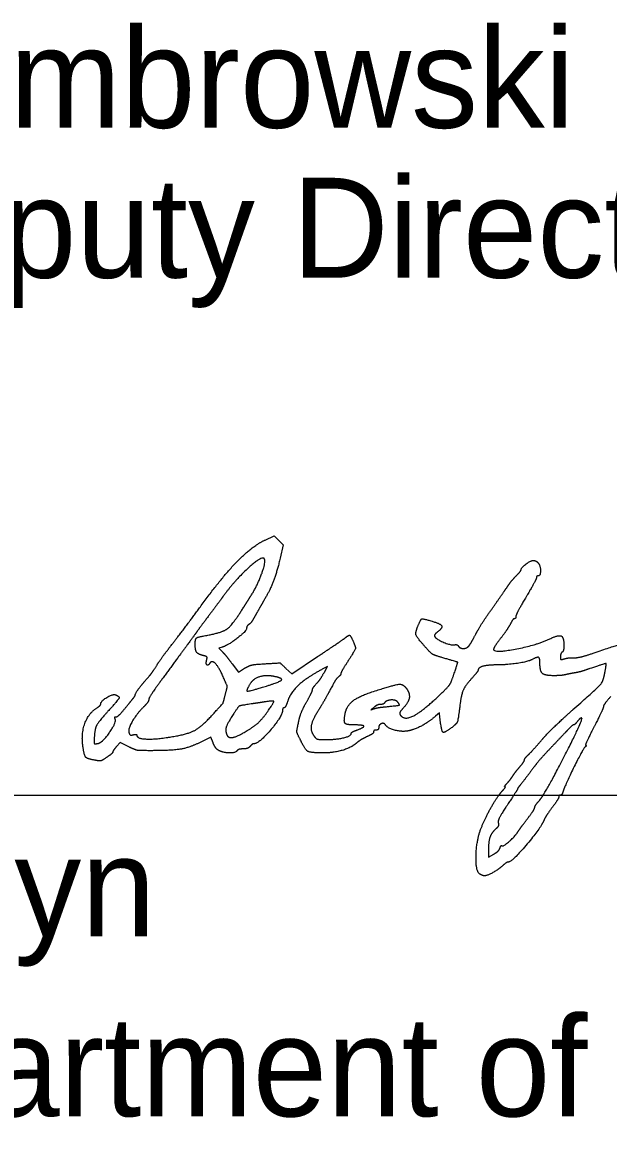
# Model space of a CAD drawing. Extents: x 0 to 34, y 0 to 22.
# Drawn here: x 25.732 to 26.552, y 7.26 to 8.834 of the extents above; entities that cross this region are included whole.
import ezdxf

# ---------------------------------------------------------------- set-up
doc = ezdxf.new("R2010")
doc.units = 0
for name, color, linetype in [('Default', 7, 'Continuous'), ('SH_Data', 7, 'Continuous'), ('SH_Text', 7, 'Continuous')]:
    doc.layers.add(name, color=color, linetype=linetype)

msp = doc.modelspace()

# ---------------------------------------------------------------- linework, layer by layer
at = {"layer": 'Default'}
for points in [[(26.0715, 8.1089), (26.0842, 8.1148), (26.0905, 8.1084), (26.0969, 8.102), (26.0925, 8.0833)], [(26.0116, 7.9589), (26.0066, 7.9574), (26.0118, 7.9522)], [(26.0254, 7.9355), (26.034, 7.924), (26.0428, 7.9293)], [(26.1006, 7.9292), (26.1087, 7.9216), (26.145, 7.9457)], [(26.1544, 7.924), (26.1589, 7.9319), (26.1534, 7.929)], [(26.3162, 7.8603), (26.3156, 7.8671), (26.3097, 7.862)], [(25.88, 7.8196), (25.8685, 7.8254), (25.8634, 7.8196)], [(25.9986, 7.8247), (25.9953, 7.8327), (25.9814, 7.8259)], [(26.384, 7.6742), (26.384, 7.6648), (26.3915, 7.6691)]]:
    msp.add_lwpolyline(points, dxfattribs=at)
for points in [[(25.982, 8.017), (26.0116, 8.0576), (26.0535, 8.1005), (26.0715, 8.1089)], [(26.0701, 8.0831), (26.0664, 8.0868), (26.0279, 8.051), (26.0125, 8.0297)], [(26.0518, 8.0311), (26.0612, 8.0459), (26.0732, 8.08), (26.0701, 8.0831)], [(26.0925, 8.0833), (26.0875, 8.0622), (26.0783, 8.0386), (26.0689, 8.0227)], [(26.4296, 8.067), (26.4296, 8.0698), (26.4428, 8.0801), (26.4465, 8.0802)], [(26.4465, 8.0802), (26.4485, 8.0802), (26.4515, 8.079), (26.4531, 8.0774)], [(26.4531, 8.0774), (26.4566, 8.0739), (26.457, 8.0587), (26.4536, 8.0587)], [(26.423, 8.0589), (26.4266, 8.0625), (26.4296, 8.0662), (26.4296, 8.067)], [(26.4092, 8.0417), (26.4131, 8.0475), (26.4193, 8.0553), (26.423, 8.0589)], [(26.4512, 8.0561), (26.4512, 8.0548), (26.4447, 8.0427), (26.4368, 8.0293)], [(26.4536, 8.0587), (26.4523, 8.0587), (26.4512, 8.0575), (26.4512, 8.0561)], [(26.0125, 8.0297), (26.0089, 8.0248), (25.9995, 8.0121), (25.9916, 8.0016)], [(26.0413, 8.0144), (26.0445, 8.0196), (26.0493, 8.0271), (26.0518, 8.0311)], [(26.3876, 8.0107), (26.3955, 8.0219), (26.4052, 8.0358), (26.4092, 8.0417)], [(26.4368, 8.0293), (26.4289, 8.0159), (26.4224, 8.0035), (26.4224, 8.0018)], [(25.9418, 7.9636), (25.9507, 7.9749), (25.9688, 7.999), (25.982, 8.017)], [(25.9915, 7.9757), (26.0121, 7.9795), (26.0261, 7.9904), (26.0413, 8.0144)], [(26.0689, 8.0227), (26.0654, 8.0167), (26.0602, 8.0075), (26.0573, 8.0023)], [(25.9916, 8.0016), (25.9837, 7.9912), (25.9756, 7.9801), (25.9736, 7.9772)], [(26.0573, 8.0023), (26.0545, 7.997), (26.0507, 7.9918), (26.0489, 7.9907)], [(26.2855, 7.9889), (26.2893, 7.998), (26.2924, 7.999), (26.3051, 7.9952)], [(26.3662, 7.9771), (26.37, 7.9843), (26.3796, 7.9994), (26.3876, 8.0107)], [(26.4204, 7.9987), (26.4193, 7.9987), (26.4169, 7.9957), (26.4151, 7.9921)], [(26.4224, 8.0018), (26.4224, 8.0001), (26.4215, 7.9987), (26.4204, 7.9987)], [(26.0456, 7.9853), (26.0456, 7.9816), (26.0198, 7.9615), (26.0116, 7.9589)], [(26.0489, 7.9907), (26.0471, 7.9897), (26.0456, 7.9873), (26.0456, 7.9853)], [(26.2953, 7.9595), (26.2838, 7.9726), (26.2815, 7.9793), (26.2855, 7.9889)], [(26.3051, 7.9952), (26.3171, 7.9917), (26.32, 7.9855), (26.3123, 7.9797)], [(26.4151, 7.9921), (26.4133, 7.9884), (26.4072, 7.9793), (26.4015, 7.9719)], [(25.9736, 7.9772), (25.9716, 7.9742), (25.9562, 7.9533), (25.9394, 7.9306)], [(25.9736, 7.9636), (25.9736, 7.9705), (25.9777, 7.9733), (25.9915, 7.9757)], [(26.145, 7.9457), (26.1649, 7.959), (26.1825, 7.9709), (26.1841, 7.9723)], [(26.1841, 7.9723), (26.1886, 7.976), (26.191, 7.9751), (26.194, 7.9685)], [(26.194, 7.9685), (26.1984, 7.9589), (26.1974, 7.9548), (26.1872, 7.939)], [(26.3123, 7.9797), (26.3095, 7.9776), (26.3081, 7.9748), (26.309, 7.9734)], [(26.309, 7.9734), (26.3117, 7.9696), (26.3316, 7.9614), (26.3362, 7.9622)], [(26.3569, 7.9609), (26.3582, 7.9625), (26.3624, 7.9698), (26.3662, 7.9771)], [(26.4015, 7.9719), (26.3958, 7.9644), (26.3912, 7.9571), (26.3912, 7.9558)], [(26.3912, 7.9558), (26.3912, 7.9505), (26.4508, 7.9615), (26.4688, 7.97)], [(26.4688, 7.97), (26.4817, 7.9762), (26.4896, 7.9731), (26.4896, 7.9617)], [(25.9203, 7.9342), (25.9232, 7.939), (25.9329, 7.9522), (25.9418, 7.9636)], [(25.9846, 7.9472), (25.9774, 7.949), (25.9736, 7.9547), (25.9736, 7.9636)], [(26.0118, 7.9522), (26.0146, 7.9494), (26.0207, 7.9419), (26.0254, 7.9355)], [(26.3188, 7.9444), (26.308, 7.9475), (26.3031, 7.9506), (26.2953, 7.9595)], [(26.3362, 7.9622), (26.3385, 7.9626), (26.341, 7.9618), (26.3419, 7.9604)], [(26.3419, 7.9604), (26.3441, 7.9569), (26.3541, 7.9572), (26.3569, 7.9609)], [(26.4872, 7.9519), (26.4859, 7.951), (26.4848, 7.9482), (26.4848, 7.9456)], [(26.4896, 7.9617), (26.4896, 7.9571), (26.4885, 7.9527), (26.4872, 7.9519)], [(26.5031, 7.9439), (26.5073, 7.9438), (26.5202, 7.9469), (26.5319, 7.9509)], [(26.5319, 7.9509), (26.5723, 7.9648), (26.5782, 7.9632), (26.5741, 7.9393)], [(25.904, 7.9123), (25.9106, 7.9197), (25.9148, 7.9254), (25.9203, 7.9342)], [(25.9897, 7.941), (25.9906, 7.9445), (25.9893, 7.946), (25.9846, 7.9472)], [(25.9939, 7.9362), (25.9915, 7.9323), (25.9883, 7.9359), (25.9897, 7.941)], [(26.0127, 7.9176), (26.0066, 7.9313), (25.9969, 7.9409), (25.9939, 7.9362)], [(26.0428, 7.9293), (26.0493, 7.9331), (26.0569, 7.9348), (26.072, 7.9357)], [(26.072, 7.9357), (26.0923, 7.9369), (26.0925, 7.9368), (26.1006, 7.9292)], [(26.1872, 7.939), (26.1819, 7.9308), (26.1776, 7.9232), (26.1776, 7.9221)], [(26.3356, 7.9206), (26.3412, 7.9374), (26.3409, 7.938), (26.3188, 7.9444)], [(26.3938, 7.9339), (26.3823, 7.9339), (26.3696, 7.9301), (26.3696, 7.9267)], [(26.4445, 7.9412), (26.439, 7.9383), (26.4088, 7.9339), (26.3938, 7.9339)], [(26.456, 7.9365), (26.456, 7.9439), (26.4523, 7.9454), (26.4445, 7.9412)], [(26.4753, 7.9189), (26.4629, 7.9189), (26.456, 7.9252), (26.456, 7.9365)], [(26.4848, 7.9456), (26.4848, 7.9417), (26.4858, 7.9411), (26.4902, 7.9425)], [(26.4902, 7.9425), (26.4931, 7.9434), (26.499, 7.9441), (26.5031, 7.9439)], [(26.5472, 7.9243), (26.5493, 7.9358), (26.5475, 7.9362), (26.5265, 7.929)], [(25.9394, 7.9306), (25.9226, 7.908), (25.9088, 7.8878), (25.9088, 7.8859)], [(26.0838, 7.9179), (26.0729, 7.9201), (26.0555, 7.915), (26.0512, 7.9084)], [(26.1534, 7.929), (26.13, 7.9164), (26.1072, 7.8958), (26.1031, 7.8833)], [(26.1417, 7.9058), (26.1471, 7.9118), (26.1496, 7.9154), (26.1544, 7.924)], [(26.1776, 7.9221), (26.1776, 7.921), (26.176, 7.9187), (26.174, 7.9171)], [(26.3173, 7.8933), (26.3277, 7.9033), (26.3318, 7.9095), (26.3356, 7.9206)], [(26.3696, 7.9267), (26.3696, 7.9258), (26.3654, 7.9204), (26.3602, 7.9146)], [(26.492, 7.9203), (26.4887, 7.9195), (26.4812, 7.9189), (26.4753, 7.9189)], [(26.5052, 7.9229), (26.5012, 7.9223), (26.4953, 7.9211), (26.492, 7.9203)], [(26.5023, 7.8714), (26.5378, 7.9029), (26.5448, 7.9111), (26.5472, 7.9243)], [(26.5265, 7.929), (26.5188, 7.9263), (26.5091, 7.9235), (26.5052, 7.9229)], [(25.8896, 7.8919), (25.8896, 7.8935), (25.8987, 7.9065), (25.904, 7.9123)], [(26.016, 7.8931), (26.0186, 7.9029), (26.0183, 7.9051), (26.0127, 7.9176)], [(26.0512, 7.9084), (26.0442, 7.8977), (26.0487, 7.8969), (26.0732, 7.9044)], [(26.0732, 7.9044), (26.0924, 7.9103), (26.0964, 7.9154), (26.0838, 7.9179)], [(26.1377, 7.8988), (26.1379, 7.9006), (26.1397, 7.9037), (26.1417, 7.9058)], [(26.1671, 7.9078), (26.159, 7.8924), (26.1512, 7.8786), (26.1451, 7.8689)], [(26.174, 7.9171), (26.1721, 7.9155), (26.169, 7.9113), (26.1671, 7.9078)], [(26.221, 7.8961), (26.2528, 7.9067), (26.2662, 7.9071), (26.2713, 7.8977)], [(26.3602, 7.9146), (26.3517, 7.9052), (26.346, 7.8926), (26.3444, 7.8799)], [(25.8416, 7.8798), (25.8417, 7.8836), (25.8584, 7.8936), (25.8622, 7.8921)], [(25.8622, 7.8921), (25.8681, 7.8898), (25.8659, 7.8849), (25.8515, 7.869)], [(25.8751, 7.8727), (25.8804, 7.8793), (25.8859, 7.886), (25.8872, 7.8876)], [(25.8872, 7.8876), (25.8885, 7.8892), (25.8896, 7.8911), (25.8896, 7.8919)], [(25.9964, 7.8626), (26.0125, 7.8801), (26.0128, 7.8807), (26.016, 7.8931)], [(26.1292, 7.8817), (26.1336, 7.8894), (26.1374, 7.8971), (26.1377, 7.8988)], [(26.1833, 7.8651), (26.1855, 7.8763), (26.2016, 7.8897), (26.221, 7.8961)], [(26.2603, 7.8644), (26.2656, 7.8558), (26.2923, 7.8693), (26.3173, 7.8933)], [(26.2713, 7.8977), (26.2745, 7.8916), (26.2711, 7.8802), (26.2637, 7.8723)], [(26.5553, 7.8899), (26.5495, 7.8834), (26.5448, 7.8769), (26.5448, 7.8753)], [(25.8167, 7.8182), (25.8138, 7.8368), (25.8245, 7.8668), (25.8369, 7.8745)], [(25.8369, 7.8745), (25.8395, 7.8761), (25.8416, 7.8785), (25.8416, 7.8798)], [(25.8628, 7.8614), (25.8642, 7.861), (25.8697, 7.8661), (25.8751, 7.8727)], [(25.9014, 7.8751), (25.8916, 7.8655), (25.8792, 7.8434), (25.881, 7.8387)], [(25.9088, 7.8859), (25.9087, 7.8839), (25.9054, 7.8791), (25.9014, 7.8751)], [(26.054, 7.8796), (26.0362, 7.877), (26.0342, 7.8759), (26.0269, 7.8647)], [(26.0714, 7.8823), (26.0658, 7.8814), (26.0579, 7.8802), (26.054, 7.8796)], [(26.0959, 7.8709), (26.0958, 7.8623), (26.0627, 7.8235), (26.0556, 7.8235)], [(26.0764, 7.8706), (26.0842, 7.882), (26.0833, 7.8841), (26.0714, 7.8823)], [(26.098, 7.8739), (26.0969, 7.8739), (26.096, 7.8725), (26.0959, 7.8709)], [(26.1031, 7.8833), (26.1014, 7.8781), (26.0991, 7.8739), (26.098, 7.8739)], [(26.1183, 7.8539), (26.1199, 7.8616), (26.1248, 7.8741), (26.1292, 7.8817)], [(26.2242, 7.8749), (26.2196, 7.8711), (26.2196, 7.8711), (26.2244, 7.8728)], [(26.2331, 7.8787), (26.2308, 7.8787), (26.2268, 7.877), (26.2242, 7.8749)], [(26.2244, 7.8728), (26.227, 7.8737), (26.2346, 7.8749), (26.2412, 7.8755)], [(26.2386, 7.8808), (26.2379, 7.8796), (26.2354, 7.8787), (26.2331, 7.8787)], [(26.2571, 7.8819), (26.2543, 7.8853), (26.2409, 7.8845), (26.2386, 7.8808)], [(26.2412, 7.8755), (26.2579, 7.8771), (26.2603, 7.878), (26.2571, 7.8819)], [(26.2637, 7.8723), (26.2609, 7.8694), (26.2594, 7.8659), (26.2603, 7.8644)], [(26.3444, 7.8799), (26.3416, 7.8574), (26.3398, 7.8519), (26.3342, 7.8474)], [(26.4583, 7.8286), (26.4655, 7.837), (26.4853, 7.8562), (26.5023, 7.8714)], [(26.5448, 7.8753), (26.5448, 7.8737), (26.5388, 7.8609), (26.5315, 7.8467)], [(25.8515, 7.869), (25.8379, 7.8539), (25.8329, 7.8437), (25.8323, 7.8299)], [(25.8371, 7.8239), (25.8435, 7.8248), (25.8636, 7.8533), (25.8616, 7.8585)], [(25.8616, 7.8585), (25.8608, 7.8604), (25.8613, 7.8617), (25.8628, 7.8614)], [(25.9399, 7.8332), (25.9626, 7.8369), (25.9822, 7.8471), (25.9964, 7.8626)], [(26.0269, 7.8647), (26.0187, 7.852), (26.0155, 7.8422), (26.0177, 7.8364)], [(26.0465, 7.842), (26.0577, 7.8489), (26.0686, 7.8595), (26.0764, 7.8706)], [(26.1451, 7.8689), (26.1371, 7.8563), (26.1349, 7.8411), (26.14, 7.8343)], [(26.1969, 7.8499), (26.1854, 7.8499), (26.1813, 7.8544), (26.1833, 7.8651)], [(26.3097, 7.862), (26.3003, 7.8538), (26.2803, 7.8432), (26.2712, 7.8415)], [(26.3342, 7.8474), (26.3224, 7.8382), (26.3181, 7.8413), (26.3162, 7.8603)], [(26.4557, 7.7448), (26.4633, 7.7535), (26.5166, 7.8573), (26.5145, 7.8594)], [(26.5088, 7.8553), (26.5064, 7.8523), (26.5038, 7.8499), (26.503, 7.8499)], [(26.5145, 7.8594), (26.5138, 7.8601), (26.5112, 7.8582), (26.5088, 7.8553)], [(26.0177, 7.8364), (26.0198, 7.8311), (26.0333, 7.8338), (26.0465, 7.842)], [(26.1203, 7.8299), (26.1159, 7.839), (26.1157, 7.8412), (26.1183, 7.8539)], [(26.192, 7.8381), (26.192, 7.8391), (26.1957, 7.8413), (26.2002, 7.8429)], [(26.2002, 7.8429), (26.2105, 7.8467), (26.209, 7.8499), (26.1969, 7.8499)], [(26.2232, 7.8402), (26.2232, 7.8389), (26.2207, 7.8366), (26.2178, 7.8353)], [(26.2268, 7.8427), (26.2248, 7.8427), (26.2232, 7.8416), (26.2232, 7.8402)], [(26.2304, 7.846), (26.2304, 7.8442), (26.2288, 7.8427), (26.2268, 7.8427)], [(26.2399, 7.85), (26.2378, 7.8533), (26.2304, 7.8502), (26.2304, 7.846)], [(26.2712, 7.8415), (26.2626, 7.84), (26.2428, 7.8453), (26.2399, 7.85)], [(26.4942, 7.8421), (26.4901, 7.8378), (26.4796, 7.8267), (26.4708, 7.8174)], [(26.503, 7.8499), (26.5022, 7.8499), (26.4983, 7.8464), (26.4942, 7.8421)], [(26.5315, 7.8467), (26.5243, 7.8326), (26.5191, 7.821), (26.5201, 7.821)], [(25.8323, 7.8299), (25.8321, 7.8243), (25.8329, 7.8233), (25.8371, 7.8239)], [(25.881, 7.8387), (25.8819, 7.8363), (25.8842, 7.8354), (25.8872, 7.8362)], [(25.8872, 7.8362), (25.8898, 7.8369), (25.892, 7.8365), (25.892, 7.8354)], [(25.892, 7.8354), (25.892, 7.8308), (25.9176, 7.8296), (25.9399, 7.8332)], [(25.9814, 7.8259), (25.9658, 7.8181), (25.9407, 7.8139), (25.9107, 7.8139)], [(26.0068, 7.8141), (26.0041, 7.8155), (26.0005, 7.8203), (25.9986, 7.8247)], [(26.152, 7.8107), (26.1346, 7.8108), (26.1276, 7.8151), (26.1203, 7.8299)], [(26.14, 7.8343), (26.1428, 7.8305), (26.1464, 7.8295), (26.1576, 7.8295)], [(26.1986, 7.824), (26.1909, 7.8176), (26.1666, 7.8107), (26.152, 7.8107)], [(26.1576, 7.8295), (26.1716, 7.8295), (26.192, 7.8346), (26.192, 7.8381)], [(26.2178, 7.8353), (26.2104, 7.832), (26.2028, 7.8275), (26.1986, 7.824)], [(26.4398, 7.8082), (26.4428, 7.811), (26.4511, 7.8202), (26.4583, 7.8286)], [(25.8333, 7.8005), (25.8224, 7.8025), (25.8186, 7.8066), (25.8167, 7.8182)], [(25.8584, 7.812), (25.8583, 7.8111), (25.8546, 7.8077), (25.85, 7.8046)], [(25.8634, 7.8196), (25.8606, 7.8164), (25.8584, 7.813), (25.8584, 7.812)], [(25.9107, 7.8139), (25.8952, 7.8139), (25.8893, 7.815), (25.88, 7.8196)], [(26.0324, 7.8139), (26.0304, 7.8107), (26.0129, 7.8108), (26.0068, 7.8141)], [(26.0406, 7.8163), (26.0369, 7.8163), (26.0332, 7.8152), (26.0324, 7.8139)], [(26.0504, 7.8199), (26.0487, 7.8179), (26.0443, 7.8163), (26.0406, 7.8163)], [(26.0556, 7.8235), (26.0544, 7.8235), (26.052, 7.8218), (26.0504, 7.8199)], [(26.4344, 7.801), (26.4344, 7.8021), (26.4369, 7.8054), (26.4398, 7.8082)], [(26.4708, 7.8174), (26.462, 7.8082), (26.4521, 7.7969), (26.4488, 7.7924)], [(26.5194, 7.8192), (26.5167, 7.8174), (26.4915, 7.7664), (26.4885, 7.7569)], [(26.5201, 7.821), (26.5212, 7.821), (26.5208, 7.8202), (26.5194, 7.8192)], [(25.85, 7.8046), (25.8435, 7.8001), (25.8399, 7.7992), (25.8333, 7.8005)], [(26.4488, 7.7924), (26.4407, 7.7815), (26.4302, 7.7677), (26.4272, 7.7642)], [(26.4278, 7.7912), (26.4314, 7.7954), (26.4344, 7.7998), (26.4344, 7.801)], [(26.4098, 7.7679), (26.4121, 7.7703), (26.4156, 7.7748), (26.4176, 7.7778)], [(26.4176, 7.7778), (26.4196, 7.7809), (26.4241, 7.7869), (26.4278, 7.7912)], [(26.4039, 7.7581), (26.4066, 7.761), (26.4081, 7.7635), (26.4072, 7.7635)], [(26.4072, 7.7635), (26.4063, 7.7635), (26.4075, 7.7654), (26.4098, 7.7679)], [(26.4272, 7.7642), (26.4259, 7.7626), (26.4248, 7.7608), (26.4248, 7.7603)], [(26.3738, 7.7055), (26.3797, 7.7203), (26.3968, 7.7502), (26.4039, 7.7581)], [(26.4248, 7.7603), (26.4248, 7.7597), (26.4184, 7.7498), (26.4107, 7.7382)], [(26.4824, 7.749), (26.4824, 7.7476), (26.4781, 7.7408), (26.4729, 7.7339)], [(26.4846, 7.7515), (26.4834, 7.7515), (26.4824, 7.7503), (26.4824, 7.749)], [(26.4885, 7.7569), (26.4876, 7.7539), (26.4858, 7.7515), (26.4846, 7.7515)], [(26.4107, 7.7382), (26.402, 7.7251), (26.3971, 7.7154), (26.3978, 7.7127)], [(26.4386, 7.7186), (26.4442, 7.726), (26.4488, 7.7331), (26.4488, 7.7345)], [(26.4488, 7.7345), (26.4488, 7.7358), (26.4519, 7.7404), (26.4557, 7.7448)], [(26.4729, 7.7339), (26.4677, 7.727), (26.4626, 7.719), (26.4615, 7.7162)], [(26.4615, 7.7162), (26.4578, 7.7064), (26.4167, 7.6579), (26.412, 7.6579)], [(26.426, 7.7014), (26.4273, 7.7035), (26.433, 7.7113), (26.4386, 7.7186)], [(26.372, 7.641), (26.366, 7.6448), (26.3673, 7.6891), (26.3738, 7.7055)], [(26.3941, 7.7041), (26.3882, 7.6989), (26.384, 7.6865), (26.384, 7.6742)], [(26.3978, 7.7127), (26.3984, 7.7101), (26.3969, 7.7065), (26.3941, 7.7041)], [(26.4032, 7.6807), (26.4051, 7.6795), (26.4217, 7.6946), (26.426, 7.7014)], [(26.3915, 7.6691), (26.3956, 7.6715), (26.3995, 7.6753), (26.4002, 7.6776)], [(26.4002, 7.6776), (26.4008, 7.6799), (26.4022, 7.6813), (26.4032, 7.6807)], [(26.4045, 7.6533), (26.3983, 7.6476), (26.3824, 7.6387), (26.3785, 7.6387)], [(26.412, 7.6579), (26.4106, 7.6579), (26.4073, 7.6558), (26.4045, 7.6533)], [(26.3785, 7.6387), (26.3769, 7.6387), (26.374, 7.6398), (26.372, 7.641)]]:
    msp.add_open_spline(points, degree=2, dxfattribs=at)
at = {"layer": 'SH_Data'}
msp.add_line((24.5769, 7.7518), (28.0769, 7.7518), dxfattribs=at)

# ---------------------------------------------------------------- texts
at = {"layer": 'SH_Text'}
for s, p in [('Michael G. Dombrowski', (24.5279, 8.6862)), ('District       Deputy Director', (24.5279, 8.4762)), ('Pamela Boratyn', (24.5863, 7.5537)), ('Director, Department of Transportation', (24.5769, 7.3018))]:
    msp.add_text(s, height=0.14, dxfattribs=at).set_placement(p)

doc.saveas('drawing.dxf')
